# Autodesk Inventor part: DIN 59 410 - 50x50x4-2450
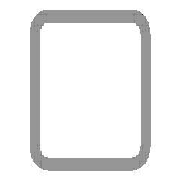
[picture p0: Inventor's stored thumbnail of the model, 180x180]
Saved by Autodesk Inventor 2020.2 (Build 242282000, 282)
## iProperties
Manager: www.cadconsulting.pl
Company: Fabian Stasiak CAD Consulting
Created: 2015-01
Part Number: DIN 59 410 - 50x50x4-2450
Material: Stal, miękka
Description: Rurki stalowe o przekroju kwadratowym formowane na gorąco
Document SubType Name: Modellieren
Standard: DIN
Designer: F.Stasiak
Standards Organization: DIN
Language: pl-PL
Size Designation: 50x50x4
Categories: <MemberInstance><Categories><Category DisplayName="Kształtowniki konstrukcyjne" InternalName="089c4875-fa83-4c05-b084-43b9cc11f5ed" Mnemonic="GRDR"><CategoryPar
Stock Number: 50x50x4
Density: 7.85 g/cm^3
Appearance: Częściowo polerowana
Mass: 13362.7 g
Surface Area: 8525.15 cm^2
Volume: 1702.25 cm^3
Catalog Web Link: www.expertbooks.pl
_CCFamilyMember: 40
_CCFamilyDisplayName: DIN 59410 (Kwadrat) - Rurki stalowe o przekroju kwadratowym formowane na gorąco
_FrameMemberDoc: Frame Member File
_Version: 15.0.0
_GetPNFromCC: 1
G_W: 50,000 mm
G_H: 50,000 mm
+C8BA9A9F-9326-41C6-A231-2A3BA002AD84+CUTDETAIL1: Wytnij
+E4B92671-9DEC-41A1-B9A1-CC49D844D9E1+CUTDETAIL2: Wytnij
G_L: 2450,000 mm
IsCustomPart: 1
Author: F.Stasiak
Subject: Zbiór ćwiczeń. Autodesk Inventor 2020. Kurs Professional
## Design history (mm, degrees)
node "Płaszczyzna początkowa"
node "Płaszczyzna końcowa"
sketch "Szkic"
  geometry: L1 (-17, 25)-(17, 25); L2 (25, 17)-(25, -17); L3 (17, -25)-(-17, -25); L4 (-25, -17)-(-25, 17); L5 (-37.32, 0)-(37.32, 0) reference; L6 (0, -37.32)-(0, 37.32) reference; L7 (-17, 21)-(17, 21); L8 (21, 17)-(21, -17); L9 (17, -21)-(-17, -21); L10 (-21, -17)-(-21, 17); A1 r 8 centre (-17, 17) between (-17, 25) and (-25, 17); A2 r 8 centre (17, 17) between (25, 17) and (17, 25); A3 r 8 centre (17, -17) between (17, -25) and (25, -17); A4 r 8 centre (-17, -17) between (-25, -17) and (-17, -25); A5 r 4 centre (-17, 17) between (-17, 21) and (-21, 17); A6 r 4 centre (17, 17) between (21, 17) and (17, 21); A7 r 4 centre (17, -17) between (17, -21) and (21, -17); A8 r 4 centre (-17, -17) between (-21, -17) and (-17, -21); 3 further points
  constraints: 16 end point, 16 point on circle, 8 centre point, 8 tangent, 6 point on line, 4 parallel, 3 equal radius, 3 perpendicular, 1 horizontal, 7 other
  dimensions: "b" = 50 distance of point (-25, 25) point (25, 25); "msp_r" = 8 radius of A1 (= 2 x ParT); "d8" = 25 distance between parallel lines of L4 L6 (= d9); "d9" = 25 distance between parallel lines of L3 L5 (= 0.5 x b); "d10" = 4 distance between parallel lines of L3 L9 (= ParT)
extrude "Bryła" new body sketch "Szkic" taper "d4" = 0 deg; stored distance "NLG" = 10
node "Driven Length"
  sketch "Sketch2"
    geometry: L1 (0, 0)-(10, 0) reference
    constraints: 2 end point, 1 horizontal
  workplane "Work Plane3"
  sketch "Sketch3"
    geometry: L1 (-2, 25)-(12, 25) reference; L2 (-2, 2475)-(12, 2475) reference
    dimensions: "d14" = 2450 distance between parallel lines of L1 L2 (derived)
node "Płaszczyzna konstrukcyjna4"
feature "Podział1"
node "Płaszczyzna konstrukcyjna5"
feature "Podział2"
body "Solid1"
other parameters: "ParT" = 4, "G_OFFSET_START" = -25 [user parameter; used in 1 equation term], "G_OFFSET_END" = -25 [user parameter; used in 1 equation term], "d11" = 25 (= -G_OFFSET_START), "d12" = 2475 (= G_OFFSET_END + B_L), "G_L" = 2450 (= d14) [user parameter], "d13" = 90 deg
